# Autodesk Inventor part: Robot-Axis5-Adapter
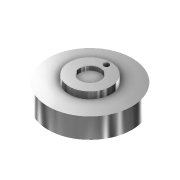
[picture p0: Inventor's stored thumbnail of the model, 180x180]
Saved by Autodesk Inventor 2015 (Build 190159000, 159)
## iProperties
Shininess: 21.0
Length Units: 11269
Angle Units: 11279
Time Units: 11290
Mass Units: 11283
Length Display Precision: 3
Angle Display Precision: 2
Created: 2001-08
Part Number: Robot-Axis5-Adapter
Document SubType Name: ﾓﾃﾞﾘﾝｸﾞ
Designer: Administrator
Density: 1 g/cm^3
Material: Generic
Appearance: Black Chrome
Density: 0.0
Volumn: 0.0
Area: 0.0
PropertySet Name: Model Information
Control State: 0
Master: False
Checked Out: False
Author: Administrator
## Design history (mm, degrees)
body "Solid1"
sketch "ｽｹｯﾁ1"
  geometry: C1 r 40 at (0, 0)
  constraints: 1 centre point
  dimensions: "d0" = 80 diameter of C1
extrude "Extrusion1" new body sketch "ｽｹｯﾁ1" distance "d1" = 19.3; taper "d2" = 0 deg
sketch "ｽｹｯﾁ2"
  geometry: C1 r 40 at (0, 0) reference; C2 r 20 at (0, 0)
  constraints: 1 centre point, 1 coincident
  dimensions: "d3" = 40 diameter of C2
extrude "Extrusion2" join sketch "ｽｹｯﾁ2" distance "d4" = 6.5; taper "d5" = 0 deg
sketch "ｽｹｯﾁ3"
  geometry: L1 (0, 0)-(0, 15.75); C1 r 20 at (0, 0) reference; C2 r 10 at (0, 0); C3 r 2.5 at (0, 15.75)
  constraints: 2 centre point, 2 coincident, 2 end point, 1 vertical
  dimensions: "d6" = 20 diameter of C2; "d9" = 15.75 distance of L1.start L1.end; "d10" = 5 diameter of C3
extrude "Extrusion3" cut sketch "ｽｹｯﾁ3" distance "d7" = 4; taper "d8" = 0 deg
